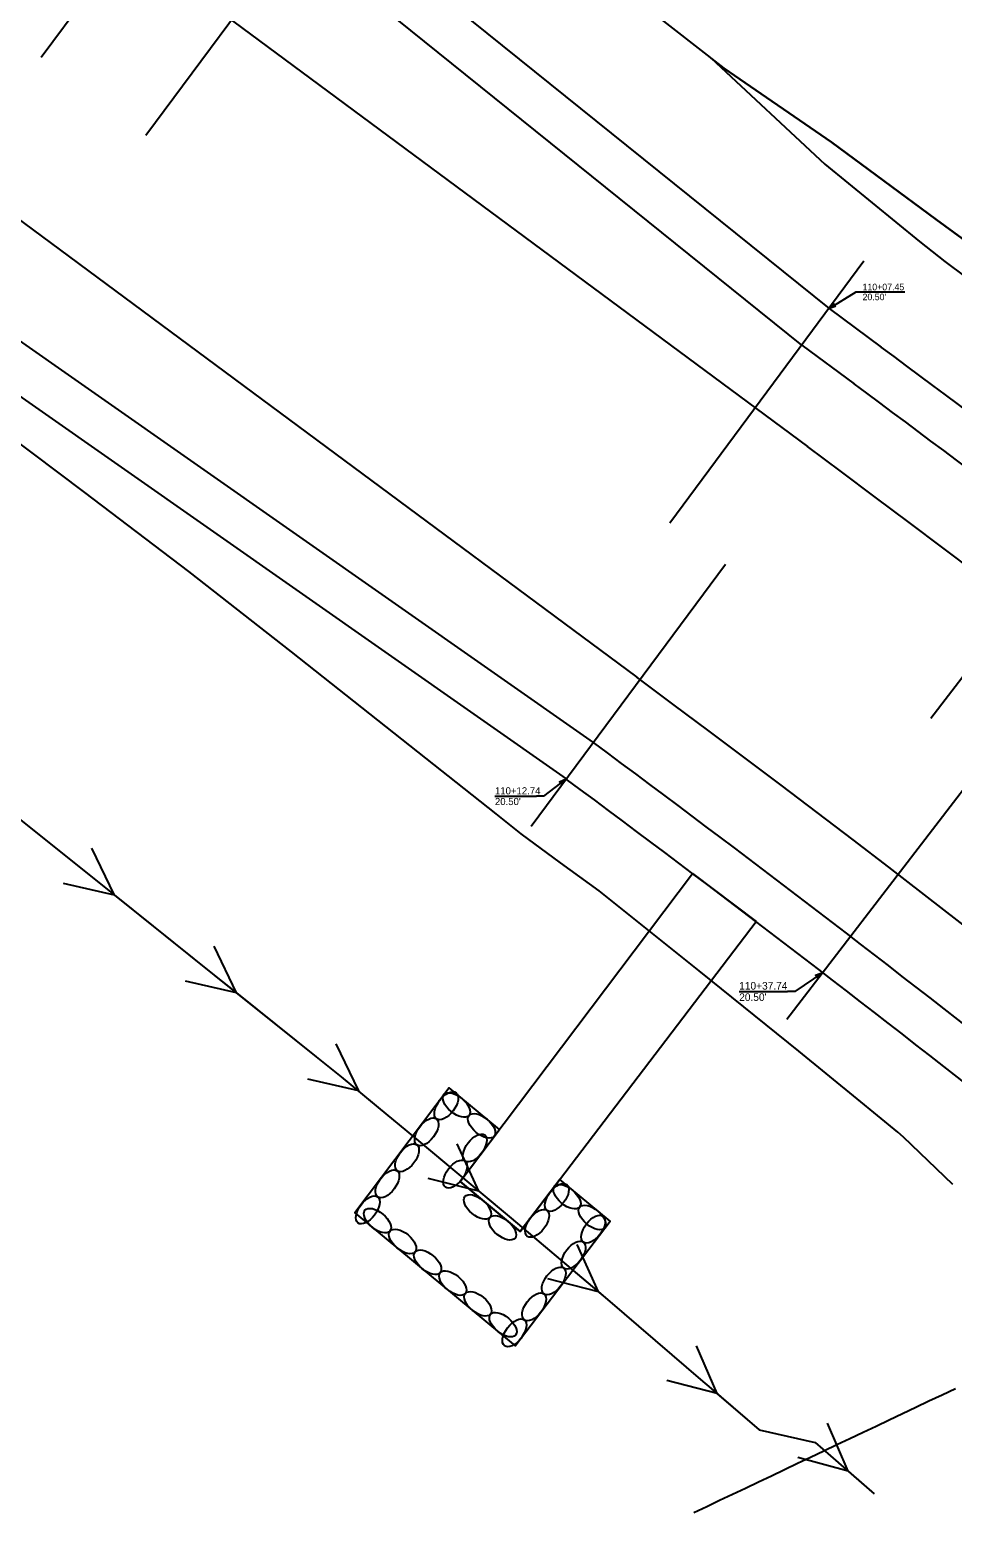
# Model space of a CAD drawing. Extents: x 1006695 to 1009377, y 1883329 to 1886115.
# Drawn here: x 1007700.6 to 1007771.4, y 1884757.7 to 1884873.3 of the extents above; entities that cross this region are included whole.
import ezdxf

# ---------------------------------------------------------------- set-up
doc = ezdxf.new("R2010")
doc.units = 0
for name, color, linetype in [('B_Bottom Cut', 7, 'Continuous'), ('B_Hatch', 7, 'Continuous'), ('R_Drainage Concrete Lining', 7, 'Continuous'), ('R_No Plot', 7, 'Continuous'), ('R_Prop Const Limits Cut', 7, 'Continuous'), ('R_Prop EOL', 7, 'Continuous'), ('R_Prop EOS', 7, 'Continuous'), ('R_Prop Guardrail', 7, 'Continuous')]:
    doc.layers.add(name, color=color, linetype=linetype)

msp = doc.modelspace()

# ---------------------------------------------------------------- linework, layer by layer
at = {"layer": 'B_Bottom Cut'}
msp.add_lwpolyline([(1007751.49, 1884759.6), (1007752.48, 1884760.07), (1007753.47, 1884760.54), (1007754.47, 1884761.01), (1007755.46, 1884761.48), (1007756.45, 1884761.96), (1007757.45, 1884762.43), (1007758.45, 1884762.9), (1007759.45, 1884763.38), (1007760.45, 1884763.85), (1007761.45, 1884764.33), (1007762.45, 1884764.81), (1007763.46, 1884765.28), (1007764.47, 1884765.76), (1007765.47, 1884766.24), (1007766.48, 1884766.72), (1007767.49, 1884767.2), (1007768.51, 1884767.68), (1007769.52, 1884768.16), (1007770.53, 1884768.64), (1007771.55, 1884769.12)], dxfattribs=at)
at = {"layer": 'B_Hatch'}
for points in [[(1007800.46, 1884835.43), (1007794.61, 1884840.48), (1007786.34, 1884846.48), (1007778.22, 1884852.68), (1007775.19, 1884854.97), (1007772.08, 1884857.31), (1007770.08, 1884858.76), (1007762.04, 1884864.71), (1007753.8, 1884870.38), (1007752.83, 1884871.14)], [(1007752.83, 1884871.14), (1007761.53, 1884863.02), (1007768.81, 1884857.07), (1007770.75, 1884855.55), (1007773.86, 1884853.21), (1007776.9, 1884850.93), (1007785.1, 1884844.84), (1007793.56, 1884838.12)], [(1007752.83, 1884871.14), (1007761.53, 1884863.02), (1007768.81, 1884857.07), (1007770.75, 1884855.55), (1007773.86, 1884853.21), (1007776.9, 1884850.93), (1007785.1, 1884844.84), (1007793.56, 1884838.12)], [(1007767.14, 1884788.77), (1007764.02, 1884791.32), (1007759.54, 1884794.99), (1007751.9, 1884801.16), (1007744.22, 1884807.28), (1007741.26, 1884809.42), (1007738.26, 1884811.66), (1007736.33, 1884813.19), (1007728.48, 1884819.4), (1007720.64, 1884825.61), (1007712.76, 1884831.78), (1007704.8, 1884837.84), (1007696.8, 1884843.83), (1007692.03, 1884847.33)], [(1007767.14, 1884788.77), (1007764.02, 1884791.32), (1007759.54, 1884794.99), (1007751.9, 1884801.16), (1007744.22, 1884807.28), (1007741.26, 1884809.42), (1007738.26, 1884811.66), (1007736.33, 1884813.19), (1007728.48, 1884819.4), (1007720.64, 1884825.61), (1007712.76, 1884831.78), (1007704.8, 1884837.84), (1007696.8, 1884843.83), (1007692.03, 1884847.33)], [(1007771.35, 1884784.76), (1007767.58, 1884788.38), (1007767.14, 1884788.77)], [(1007771.35, 1884784.76), (1007767.58, 1884788.38), (1007767.14, 1884788.77)]]:
    msp.add_lwpolyline(points, dxfattribs=at)
at = {"layer": 'R_Drainage Concrete Lining'}
for p, q in [((1007733.57, 1884784.98), (1007751.4, 1884808.61)), ((1007751.4, 1884808.61), (1007756.27, 1884804.92)), ((1007738.18, 1884781.16), (1007756.27, 1884804.92))]:
    msp.add_line(p, q, dxfattribs=at)
msp.add_lwpolyline([(1007733.57, 1884784.98), (1007738.18, 1884781.16)], dxfattribs=at)
for centre, major_axis in [((1007732.51, 1884790.8), (-0.753, -0.998)), ((1007733.29, 1884790.86), (-0.962, 0.798)), ((1007731, 1884788.8), (-0.753, -0.998)), ((1007735.22, 1884789.26), (-0.962, 0.798)), ((1007734.7, 1884787.56), (0.753, 0.998)), ((1007729.5, 1884786.81), (-0.753, -0.998)), ((1007733.19, 1884785.56), (0.753, 0.998)), ((1007727.99, 1884784.81), (-0.753, -0.998)), ((1007740.99, 1884783.77), (-0.757, -0.995)), ((1007741.77, 1884783.83), (-0.962, 0.798)), ((1007726.49, 1884782.81), (-0.753, -0.998)), ((1007734.9, 1884783.04), (-0.962, 0.798)), ((1007727.23, 1884781.99), (0.962, -0.798)), ((1007739.47, 1884781.78), (-0.757, -0.995)), ((1007743.7, 1884782.23), (-0.962, 0.798)), ((1007729.16, 1884780.39), (0.962, -0.798)), ((1007736.82, 1884781.44), (-0.962, 0.798)), ((1007743.78, 1884781.34), (0.757, 0.995)), ((1007742.27, 1884779.35), (0.757, 0.995)), ((1007731.08, 1884778.8), (0.962, -0.798)), ((1007733.01, 1884777.2), (0.962, -0.798)), ((1007740.75, 1884777.36), (0.757, 0.995)), ((1007734.93, 1884775.61), (0.962, -0.798)), ((1007739.24, 1884775.37), (0.757, 0.995)), ((1007736.86, 1884774.01), (0.962, -0.798)), ((1007737.73, 1884773.38), (0.757, 0.995))]:
    msp.add_ellipse(centre, major_axis=major_axis, ratio=0.52103, dxfattribs=at)
at = {"layer": 'R_No Plot'}
for p, q in [((1007714.84, 1884889.27), (1007701.45, 1884871.19)), ((1007764.54, 1884855.57), (1007749.66, 1884835.48)), ((1007764.43, 1884853.21), (1007767.67, 1884853.21)), ((1007784.83, 1884840.37), (1007769.67, 1884820.49)), ((1007739.03, 1884812.24), (1007753.91, 1884832.33)), ((1007758.63, 1884797.45), (1007773.87, 1884817.27)), ((1007736.24, 1884814.55), (1007739.42, 1884814.55)), ((1007707.06, 1884806.95), (1007705.34, 1884810.55)), ((1007707.06, 1884806.95), (1007703.16, 1884807.85)), ((1007716.42, 1884799.45), (1007714.7, 1884803.05)), ((1007716.42, 1884799.45), (1007712.52, 1884800.35)), ((1007754.97, 1884799.57), (1007758.67, 1884799.57)), ((1007725.79, 1884791.95), (1007724.07, 1884795.55)), ((1007725.79, 1884791.95), (1007721.89, 1884792.85)), ((1007735, 1884784.26), (1007733.35, 1884787.89)), ((1007735, 1884784.26), (1007731.12, 1884785.23)), ((1007744.18, 1884776.52), (1007742.55, 1884780.17)), ((1007744.18, 1884776.52), (1007740.3, 1884777.52)), ((1007753.29, 1884768.72), (1007751.69, 1884772.38)), ((1007753.29, 1884768.72), (1007749.42, 1884769.74)), ((1007763.32, 1884762.78), (1007761.75, 1884766.45)), ((1007763.32, 1884762.78), (1007759.46, 1884763.83))]:
    msp.add_line(p, q, dxfattribs=at)
for points in [[(1007709.48, 1884865.24), (1007720.79, 1884880.51), (1007722.87, 1884883.32)], [(1007761.86, 1884851.95), (1007763.93, 1884853.21), (1007764.43, 1884853.21)], [(1007741.71, 1884815.86), (1007739.97, 1884814.55), (1007739.42, 1884814.55)], [(1007699.09, 1884813.33), (1007706.9, 1884807.07), (1007714.71, 1884800.82), (1007722.53, 1884794.56), (1007724.46, 1884793.02), (1007727.29, 1884790.66), (1007730.06, 1884788.37), (1007737.48, 1884782.18), (1007744.86, 1884775.95), (1007752.19, 1884769.66), (1007752.63, 1884769.28), (1007756.49, 1884765.94), (1007760.79, 1884764.98), (1007762.56, 1884763.44), (1007762.59, 1884763.42), (1007765.32, 1884761.03)], [(1007699.09, 1884813.33), (1007706.9, 1884807.07), (1007707.06, 1884806.95), (1007714.71, 1884800.82), (1007716.42, 1884799.45), (1007722.53, 1884794.56), (1007724.46, 1884793.02), (1007725.77, 1884791.92), (1007727.29, 1884790.66), (1007730.06, 1884788.37), (1007735, 1884784.26), (1007737.48, 1884782.18), (1007744.18, 1884776.52), (1007744.86, 1884775.95), (1007752.19, 1884769.66), (1007752.63, 1884769.28), (1007753.28, 1884768.71), (1007756.49, 1884765.94), (1007760.79, 1884764.98), (1007762.56, 1884763.44), (1007762.59, 1884763.42), (1007763.32, 1884762.78), (1007765.32, 1884761.03)], [(1007761.38, 1884801.02), (1007759.25, 1884799.57), (1007758.67, 1884799.57)]]:
    msp.add_lwpolyline(points, dxfattribs=at)
for points in [[(1007761.86, 1884851.95), (1007762.22, 1884852.31), (1007762.34, 1884852.1)], [(1007741.71, 1884815.86), (1007741.36, 1884815.43), (1007741.2, 1884815.64)], [(1007761.38, 1884801.02), (1007760.99, 1884800.58), (1007760.83, 1884800.81)], [(1007736.58, 1884788.98), (1007732.73, 1884792.17), (1007725.49, 1884782.58), (1007737.79, 1884772.39), (1007745.07, 1884781.95), (1007741.21, 1884785.14), (1007738.18, 1884781.16), (1007733.57, 1884784.98)]]:
    msp.add_lwpolyline(points, close=True, dxfattribs=at)
at = {"layer": 'R_Prop Const Limits Cut'}
msp.add_lwpolyline([(1007745.92, 1884876.54), (1007753.8, 1884870.38), (1007762.04, 1884864.71), (1007770.08, 1884858.76), (1007772.08, 1884857.31), (1007775.19, 1884854.97), (1007778.22, 1884852.68), (1007786.34, 1884846.48), (1007794.61, 1884840.48), (1007800.46, 1884835.43)], dxfattribs=at)
at = {"layer": 'R_Prop EOL'}
for p, q in [((1007710.85, 1884877.91), (1007760.21, 1884841.35)), ((1007680.78, 1884872.81), (1007747.12, 1884823.67))]:
    msp.add_line(p, q, dxfattribs=at)
for radius, start in [(1443.39, 37.04506), (1421.39, 35.65164)]:
    msp.add_arc((1006901.08, 1883681.49), radius, start, 53.47197, dxfattribs=at)
at = {"layer": 'R_Prop EOS'}
for p, q in [((1007722.87, 1884883.32), (1007761.86, 1884851.95)), ((1007761.86, 1884851.95), (1007765.87, 1884848.98))]:
    msp.add_line(p, q, dxfattribs=at)
msp.add_lwpolyline([(1007666.92, 1884870.33), (1007672.22, 1884864.84), (1007680.25, 1884858.89), (1007741.71, 1884815.86)], dxfattribs=at)
for radius, start, end in [(1452.89, 51.92135, 53.47197), (1411.89, 51.70975, 53.45975)]:
    msp.add_arc((1006901.08, 1883681.49), radius, start, end, dxfattribs=at)
at = {"layer": 'R_Prop Guardrail'}
for p, q in [((1007759.78, 1884849.14), (1007720.79, 1884880.51)), ((1007743.79, 1884818.67), (1007682.33, 1884861.7)), ((1007759.78, 1884849.14), (1007763.78, 1884846.17))]:
    msp.add_line(p, q, dxfattribs=at)
for radius, start, end in [(1449.39, 51.92135, 53.47197), (1415.39, 51.70975, 53.45975)]:
    msp.add_arc((1006901.08, 1883681.49), radius, start, end, dxfattribs=at)

# ---------------------------------------------------------------- texts
at = {"layer": 'R_No Plot'}
for s, p in [('110+07.45', (1007764.43, 1884853.34)), ("20.50'", (1007764.43, 1884852.58))]:
    msp.add_text(s, height=0.503, rotation=360, dxfattribs=at).set_placement(p)
for s, height, p in [('110+12.74', 0.549, (1007736.24, 1884814.68)), ("20.50'", 0.549, (1007736.24, 1884813.86)), ('110+37.74', 0.582, (1007754.97, 1884799.71)), ("20.50'", 0.582, (1007754.97, 1884798.84))]:
    msp.add_text(s, height=height, dxfattribs=at).set_placement(p)

doc.saveas('drawing.dxf')
